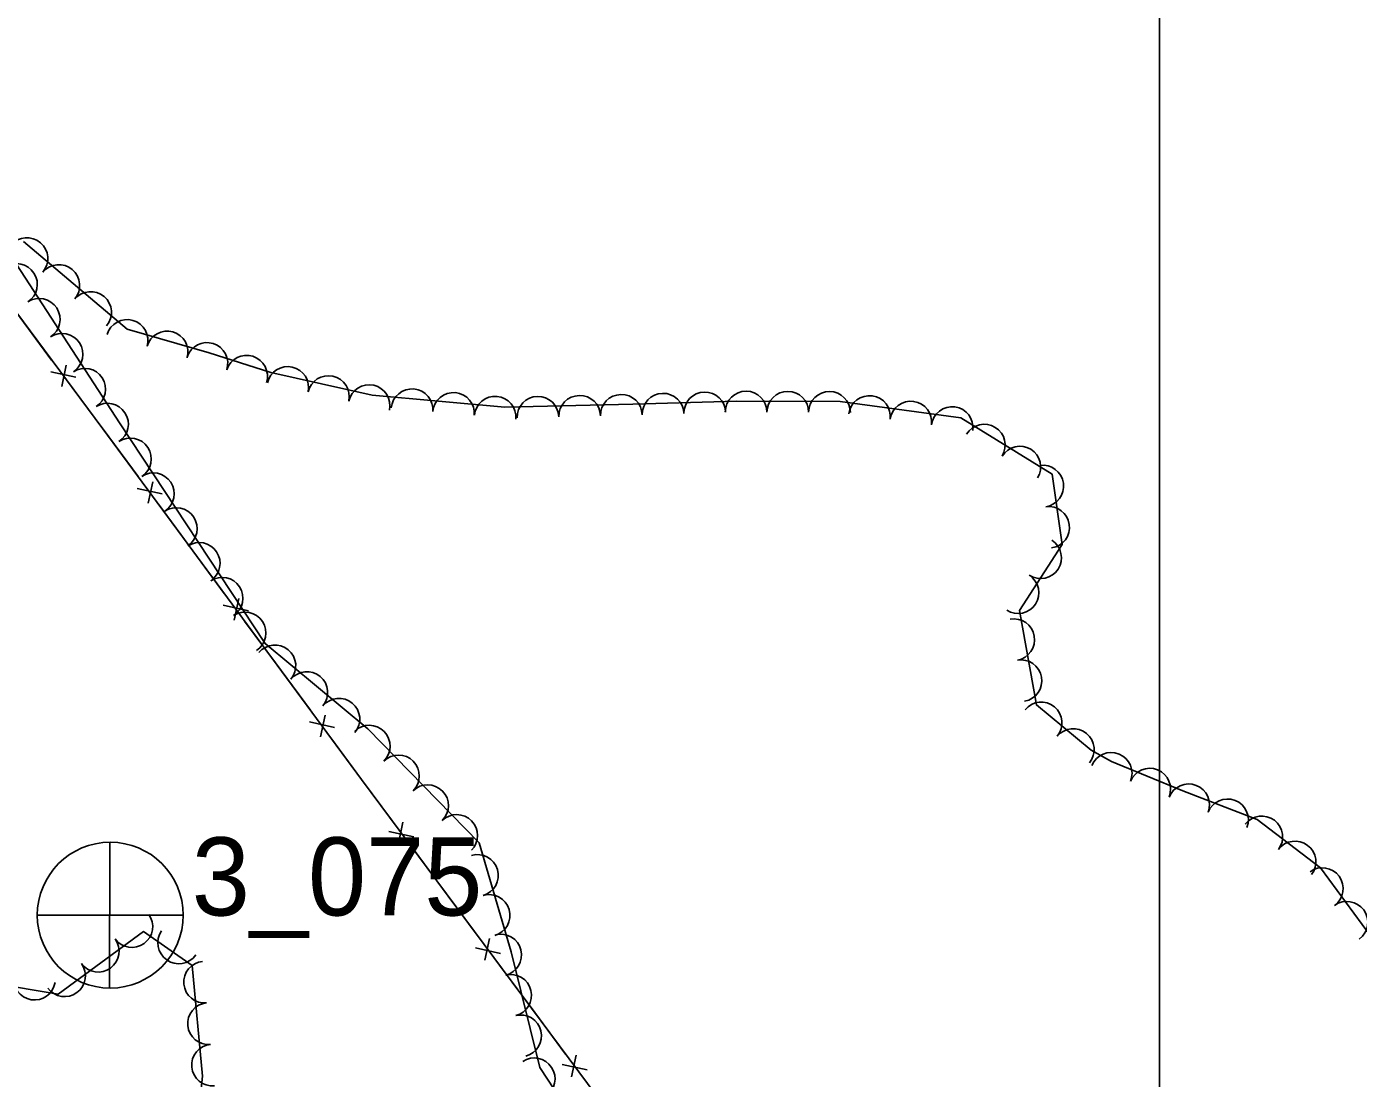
# Model space of a CAD drawing. Extents: x 353423 to 364002, y 127000 to 201942.
# Drawn here: x 360782.5 to 361038.1, y 130752.7 to 130954.6 of the extents above; entities that cross this region are included whole.
import ezdxf

# ---------------------------------------------------------------- set-up
doc = ezdxf.new("R2010")
doc.units = 0
for name, color, linetype in [('E_DTM_SlopeBottom', 7, 'Continuous'), ('E_FEN_Generic', 7, 'Continuous'), ('E_LAND_TreeLine', 7, 'Continuous'), ('E_RDWY_Gravel', 7, 'Continuous')]:
    doc.layers.add(name, color=color, linetype=linetype)

msp = doc.modelspace()

# ---------------------------------------------------------------- linework, layer by layer
at = {"layer": 'E_DTM_SlopeBottom'}
for p, q in [((360789.28, 130885.5), (360790.16, 130889.63)), ((360791.98, 130887.29), (360787.17, 130888.35)), ((360805.85, 130863.1), (360806.74, 130867.24)), ((360808.56, 130864.89), (360803.74, 130865.96)), ((360825.1, 130842.48), (360820.29, 130843.54)), ((360822.39, 130840.69), (360823.28, 130844.82)), ((360841.64, 130820.06), (360836.83, 130821.13)), ((360838.94, 130818.27), (360839.83, 130822.41)), ((360852.08, 130800.12), (360856.89, 130799.07)), ((360854.78, 130801.92), (360853.9, 130797.78)), ((360871.39, 130779.55), (360870.51, 130775.41)), ((360868.69, 130777.75), (360873.5, 130776.7)), ((360888, 130757.18), (360887.12, 130753.04)), ((360885.3, 130755.39), (360890.11, 130754.33))]:
    msp.add_line(p, q, dxfattribs=at)
for points in [[(360846.85, 130810.08), (360797.17, 130877.39), (360745.71, 130946.7), (360683.64, 131031.59), (360622.34, 131114.26), (360585.07, 131164.23), (360537.48, 131228.34), (360481.2, 131304.74), (360413.99, 131394.8), (360339.31, 131495.85), (360284.37, 131569.67), (360237.23, 131634.52), (360168.57, 131726.41)], [(360787.35, 130890.61), (360780.61, 130899.7)], [(360797.21, 130877.33), (360797.17, 130877.39), (360791.28, 130885.32)], [(360803.94, 130868.22), (360797.21, 130877.33)], [(360813.76, 130854.91), (360807.85, 130862.93)], [(360820.48, 130845.81), (360813.76, 130854.91)], [(360830.3, 130832.5), (360824.39, 130840.51)], [(360837.03, 130823.39), (360830.3, 130832.5)], [(360846.85, 130810.08), (360840.93, 130818.09)], [(360846.85, 130810.08), (360908.35, 130727.26), (360954.66, 130665.09), (360999.85, 130604.94), (361003.12, 130600.39)], [(360846.85, 130810.08), (360852.78, 130802.09)], [(360856.71, 130796.8), (360863.46, 130787.71)], [(360863.46, 130787.71), (360869.39, 130779.72)], [(360873.32, 130774.44), (360880.06, 130765.35)], [(360880.06, 130765.35), (360886, 130757.35)]]:
    msp.add_lwpolyline(points, dxfattribs=at)
at = {"layer": 'E_FEN_Generic'}
for points in [[(360869.4, 130797.96), (360848.01, 130819.78), (360828.31, 130836.19), (360800.4, 130878.57), (360762.41, 130936.85)], [(361040.47, 130780.05), (361030.91, 130793.14), (361018.71, 130802.39), (361004.43, 130807.92), (360990.74, 130813.51), (360986.89, 130815.71), (360976.34, 130824.41), (360973.13, 130842.53), (360981.29, 130855.19), (360979.37, 130868.7), (360961.87, 130879.52), (360938.72, 130882.64), (360918.88, 130882.73), (360898.92, 130882.13), (360874.33, 130881.57), (360848.85, 130883.87), (360829.4, 130888.23), (360817.6, 130892.01), (360801.85, 130896.55), (360781.97, 130913.37)], [(361133.77, 130580.83), (361061.93, 130587.22), (361046.46, 130587.42), (361022.95, 130581.54), (361013.47, 130583.51), (361003.1, 130594.19), (360995.31, 130612.43), (360975.76, 130633.5), (360964.82, 130645.32), (360957.35, 130667.6), (360938.19, 130695.02), (360926.31, 130709.37), (360910.2, 130725.5), (360888.14, 130743.99), (360881.04, 130754.82), (360875.54, 130777.02), (360869.4, 130797.96)], [(360775.92, 130770.98), (360788.58, 130768.9), (360804.99, 130780.88), (360814.31, 130774.36), (360816.31, 130753.13), (360813.35, 130725.2)]]:
    msp.add_lwpolyline(points, dxfattribs=at)
for centre, start, end in [((360782.62, 130910.08), 319.7685, 139.7531), ((360780.6, 130905.11), 303.1113, 123.096), ((360788.73, 130904.91), 319.7685, 139.7531), ((360784.97, 130898.41), 303.1113, 123.096), ((360794.84, 130899.74), 319.7685, 139.7531), ((360801.83, 130894.37), 343.9417, 163.9264), ((360789.34, 130891.71), 303.1113, 123.096), ((360809.52, 130892.16), 343.9417, 163.9264), ((360817.15, 130889.96), 342.2174, 162.2021), ((360793.7, 130885.01), 303.1113, 123.096), ((360824.77, 130887.51), 342.2174, 162.2021), ((360832.66, 130885.35), 347.3754, 167.36), ((360840.47, 130883.6), 347.3754, 167.36), ((360848.28, 130881.85), 347.3754, 167.36), ((360856.52, 130881.07), 354.8657, 174.8504), ((360864.49, 130880.36), 354.8657, 174.8504), ((360896.69, 130879.99), 1.3029, 181.2876), ((360904.71, 130880.21), 1.7354, 181.72), ((360912.71, 130880.45), 1.7354, 181.72), ((360920.63, 130880.63), 359.7449, 179.7296), ((360928.64, 130880.59), 359.7449, 179.7296), ((360936.64, 130880.56), 359.7449, 179.7296), ((360798.07, 130878.31), 303.1113, 123.096), ((360872.46, 130879.64), 354.8657, 174.8504), ((360880.69, 130879.62), 1.3029, 181.2876), ((360888.69, 130879.8), 1.3029, 181.2876), ((360944.32, 130879.77), 352.3297, 172.3144), ((360952.25, 130878.7), 352.3297, 172.3144), ((360960.18, 130877.64), 352.3297, 172.3144), ((360966.36, 130874.28), 328.2714, 148.2561), ((360802.47, 130871.62), 303.3765, 123.3611), ((360973.17, 130870.07), 328.2714, 148.2561), ((360806.87, 130864.94), 303.3765, 123.3611), ((360977.58, 130866.41), 278.111, 98.0957), ((360811.27, 130858.26), 303.3765, 123.3611), ((360978.71, 130858.49), 278.111, 98.0957), ((360977.16, 130852.65), 237.1902, 57.1748), ((360815.67, 130851.57), 303.3765, 123.3611), ((360820.07, 130844.89), 303.3765, 123.3611), ((360972.83, 130845.93), 237.1902, 57.1748), ((360824.47, 130838.21), 303.3765, 123.3611), ((360972, 130836.93), 280.0564, 100.0411), ((360830.2, 130831.9), 320.2183, 140.2029), ((360973.39, 130829.05), 280.0564, 100.0411), ((360836.34, 130826.78), 320.2183, 140.2029), ((360842.49, 130821.66), 320.2183, 140.2029), ((360977.26, 130820.94), 320.5283, 140.513), ((360848.31, 130816.49), 314.4361, 134.4208), ((360983.44, 130815.85), 320.5283, 140.513), ((360990.7, 130811.27), 337.7789, 157.7635), ((360853.91, 130810.78), 314.4361, 134.4208), ((360998.11, 130808.24), 337.7789, 157.7635), ((360859.51, 130805.07), 314.4361, 134.4208), ((361005.57, 130805.23), 338.8444, 158.8291), ((361013.03, 130802.34), 338.8444, 158.8291), ((360865.1, 130799.35), 314.4361, 134.4208), ((361019.62, 130799.07), 322.8287, 142.8134), ((361025.99, 130794.24), 322.8287, 142.8134), ((360869.06, 130791.68), 286.359, 106.3437), ((361031.23, 130789.14), 306.1564, 126.1411), ((360871.31, 130784), 286.359, 106.3437), ((361035.95, 130782.68), 306.1564, 126.1411), ((360802.75, 130781.84), 216.1254, 36.1101), ((360796.29, 130777.12), 216.1254, 36.1101), ((360811.73, 130778.72), 145.026, 325.0107), ((360873.54, 130776.41), 283.9112, 103.8959), ((360789.83, 130772.41), 216.1254, 36.1101), ((360816.71, 130771.19), 95.4069, 275.3916), ((360784.06, 130771.76), 170.6799, 350.6646), ((360875.46, 130768.65), 283.9112, 103.8959), ((360817.46, 130763.22), 95.4069, 275.3916), ((360877.38, 130760.88), 283.9112, 103.8959), ((360818.22, 130755.26), 95.4069, 275.3916), ((360879.97, 130752.64), 303.2678, 123.2525)]:
    msp.add_arc(centre, 4, start, end, dxfattribs=at)
at = {"layer": 'E_LAND_TreeLine'}
msp.add_line((361000, 129000), (361000, 131500), dxfattribs=at)
at = {"layer": 'E_RDWY_Gravel'}
for p, q in [((360798.54, 130798.08), (360798.47, 130770.22)), ((360798.54, 130798.08), (360798.47, 130770.22)), ((360784.63, 130784.05), (360812.53, 130784.03)), ((360784.63, 130784.05), (360812.53, 130784.03))]:
    msp.add_line(p, q, dxfattribs=at)
msp.add_circle((360798.59, 130784.05), 14, dxfattribs=at)
msp.add_circle((360798.59, 130784.05), 14, dxfattribs=at)

# ---------------------------------------------------------------- texts
msp.add_text('3_075', height=15, dxfattribs=at).set_placement((360814.24, 130783.98))
msp.add_text('3_075', height=15, dxfattribs=at).set_placement((360814.24, 130783.98))

doc.saveas('drawing.dxf')
